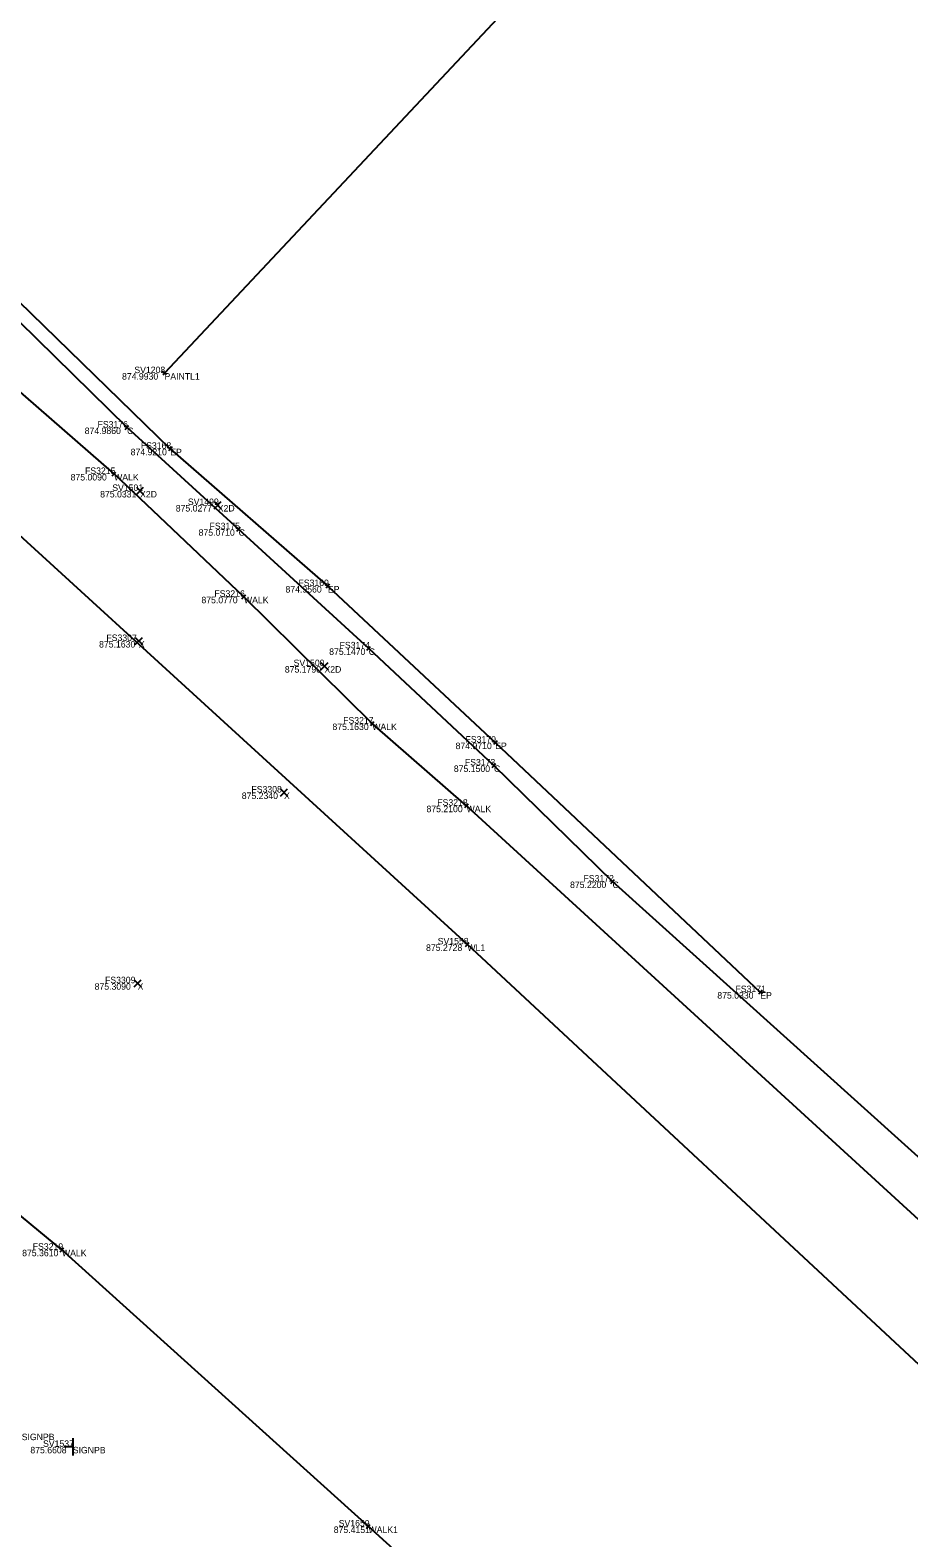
# Model space of a CAD drawing. Extents: x 1479481 to 1575806, y 316056 to 379927.
# Drawn here: x 1480189.17 to 1480197.29, y 379370.17 to 379384.1 of the extents above; entities that cross this region are included whole.
import ezdxf

# ---------------------------------------------------------------- set-up
doc = ezdxf.new("R2010")
doc.units = 0
for name, color, linetype in [('PM_X_Crosswalk', 7, 'Continuous'), ('PV_X_Curb', 7, 'Continuous'), ('PV_X_EOP', 7, 'Continuous'), ('PV_X_Walk', 7, 'Continuous'), ('SN_X_Public', 7, 'Continuous'), ('SV_X_Random_Point', 7, 'Continuous'), ('SV_X_Shot_Marker', 7, 'Continuous'), ('SV_X_Text_Comment', 7, 'Continuous'), ('SV_X_Text_Elevation', 7, 'Continuous'), ('SV_X_Text_Name', 7, 'Continuous'), ('UT_X_Water', 7, 'Continuous')]:
    doc.layers.add(name, color=color, linetype=linetype)

msp = doc.modelspace()

# ---------------------------------------------------------------- linework, layer by layer
at = {"layer": 'PM_X_Crosswalk'}
msp.add_lwpolyline([(1480217.07, 379409.327), (1480190.411, 379380.931)], dxfattribs=at)
at = {"layer": 'PV_X_Curb'}
for points in [[(1480200.436, 379370.31), (1480193.202, 379376.933), (1480192.331, 379377.692), (1480191.145, 379378.864), (1480189.945, 379379.999), (1480188.405, 379381.34), (1480186.948, 379382.631), (1480185.159, 379383.837), (1480183.612, 379384.764), (1480182.42, 379385.277), (1480180.94, 379385.773), (1480179.383, 379386.306), (1480178.708, 379386.55), (1480176.982, 379386.784), (1480175.084, 379387.087), (1480173.11, 379387.257), (1480172.166, 379387.208), (1480170.557, 379387.026), (1480168.815, 379386.8), (1480167.667, 379386.487), (1480166.614, 379386.24), (1480165.014, 379385.711), (1480163.297, 379385.035), (1480160.165, 379383.332)], [(1480200.731, 379370.664), (1480194.552, 379376.232), (1480193.456, 379377.305), (1480192.298, 379378.387), (1480191.096, 379379.488), (1480190.065, 379380.428), (1480189.066, 379381.408), (1480187.797, 379382.465), (1480186.696, 379383.309), (1480185.265, 379384.273), (1480183.824, 379385.018), (1480182.233, 379385.673), (1480180.762, 379386.381), (1480178.806, 379386.86)]]:
    msp.add_lwpolyline(points, dxfattribs=at)
at = {"layer": 'PV_X_EOP'}
msp.add_lwpolyline([(1480162.636, 379385.472), (1480163.801, 379386.077), (1480165.418, 379386.485), (1480167.155, 379386.981), (1480168.73, 379387.376), (1480170.459, 379387.707), (1480172.465, 379387.875), (1480174.363, 379387.724), (1480176.285, 379387.6), (1480178.413, 379387.246), (1480180.385, 379386.755), (1480182.516, 379385.858), (1480184.495, 379384.826), (1480186.137, 379383.794), (1480187.578, 379382.895), (1480189.061, 379381.596), (1480190.464, 379380.232), (1480191.921, 379378.963), (1480193.467, 379377.516), (1480195.917, 379375.21)], dxfattribs=at)
at = {"layer": 'PV_X_Walk'}
for points in [[(1480189.463, 379372.829), (1480188.36, 379373.736), (1480187.048, 379374.83), (1480185.76, 379375.931), (1480184.672, 379376.824), (1480183.309, 379377.92), (1480181.92, 379379.052), (1480180.82, 379379.987), (1480179.405, 379381.013), (1480178.224, 379381.663), (1480176.75, 379382.48), (1480175.258, 379382.991), (1480173.616, 379383.331), (1480171.941, 379383.389), (1480170.042, 379383.312), (1480168.62, 379383.135), (1480167.121, 379382.898), (1480164.933, 379381.864)], [(1480327.959, 379242.083), (1480313.163, 379256.356), (1480297.576, 379270.674), (1480283.951, 379284.205), (1480267.344, 379299.69), (1480258.509, 379307.782), (1480244.036, 379321.372), (1480229.243, 379335.021), (1480213.414, 379349.982), (1480196.806, 379366.202), (1480192.296, 379370.271), (1480189.463, 379372.829)]]:
    msp.add_lwpolyline(points, dxfattribs=at)
at = {"layer": 'SN_X_Public'}
for p, q in [((1480189.563, 379371.087), (1480189.563, 379370.927)), ((1480189.563, 379371.007), (1480189.483, 379371.007))]:
    msp.add_line(p, q, dxfattribs=at)
at = {"layer": 'SV_X_Random_Point'}
for p, q in [((1480190.152, 379379.809), (1480190.218, 379379.876)), ((1480190.152, 379379.876), (1480190.218, 379379.809)), ((1480190.87, 379379.678), (1480190.936, 379379.745)), ((1480190.87, 379379.745), (1480190.936, 379379.678)), ((1480190.141, 379378.422), (1480190.207, 379378.488)), ((1480190.141, 379378.488), (1480190.207, 379378.422)), ((1480191.856, 379378.189), (1480191.922, 379378.256)), ((1480191.856, 379378.256), (1480191.922, 379378.189)), ((1480191.482, 379377.022), (1480191.548, 379377.088)), ((1480191.482, 379377.088), (1480191.548, 379377.022)), ((1480190.129, 379375.259), (1480190.195, 379375.325)), ((1480190.129, 379375.325), (1480190.195, 379375.259))]:
    msp.add_line(p, q, dxfattribs=at)
at = {"layer": 'SV_X_Shot_Marker'}
for p, q in [((1480190.429, 379380.914), (1480190.393, 379380.948)), ((1480190.428, 379380.949), (1480190.394, 379380.912)), ((1480190.411, 379380.931), (1480190.411, 379380.931)), ((1480190.083, 379380.411), (1480190.047, 379380.445)), ((1480190.048, 379380.41), (1480190.082, 379380.446)), ((1480190.065, 379380.428), (1480190.065, 379380.428)), ((1480190.446, 379380.249), (1480190.482, 379380.215)), ((1480190.481, 379380.25), (1480190.447, 379380.214)), ((1480190.464, 379380.232), (1480190.464, 379380.232)), ((1480189.963, 379379.982), (1480189.927, 379380.016)), ((1480189.928, 379379.981), (1480189.962, 379380.017)), ((1480189.945, 379379.999), (1480189.945, 379379.999)), ((1480191.114, 379379.471), (1480191.078, 379379.505)), ((1480191.079, 379379.47), (1480191.113, 379379.506)), ((1480191.096, 379379.488), (1480191.096, 379379.488)), ((1480191.902, 379378.979), (1480191.94, 379378.947)), ((1480191.937, 379378.982), (1480191.905, 379378.944)), ((1480191.127, 379378.846), (1480191.163, 379378.882)), ((1480191.163, 379378.846), (1480191.127, 379378.882)), ((1480191.145, 379378.864), (1480191.145, 379378.864)), ((1480191.921, 379378.963), (1480191.921, 379378.963)), ((1480192.316, 379378.37), (1480192.28, 379378.404)), ((1480192.281, 379378.369), (1480192.315, 379378.405)), ((1480192.298, 379378.387), (1480192.298, 379378.387)), ((1480192.35, 379377.676), (1480192.312, 379377.708)), ((1480192.315, 379377.673), (1480192.347, 379377.711)), ((1480192.331, 379377.692), (1480192.331, 379377.692)), ((1480193.449, 379377.533), (1480193.485, 379377.499)), ((1480193.484, 379377.534), (1480193.45, 379377.498)), ((1480193.467, 379377.516), (1480193.467, 379377.516)), ((1480193.474, 379377.288), (1480193.438, 379377.323)), ((1480193.439, 379377.287), (1480193.473, 379377.323)), ((1480193.456, 379377.305), (1480193.456, 379377.305)), ((1480193.22, 379376.916), (1480193.184, 379376.95)), ((1480193.185, 379376.915), (1480193.219, 379376.951)), ((1480193.202, 379376.933), (1480193.202, 379376.933)), ((1480194.571, 379376.215), (1480194.533, 379376.249)), ((1480194.535, 379376.213), (1480194.569, 379376.251)), ((1480194.552, 379376.232), (1480194.552, 379376.232)), ((1480193.228, 379375.634), (1480193.192, 379375.668)), ((1480193.193, 379375.633), (1480193.227, 379375.67)), ((1480193.21, 379375.651), (1480193.21, 379375.651)), ((1480195.899, 379375.227), (1480195.935, 379375.193)), ((1480195.934, 379375.228), (1480195.9, 379375.192)), ((1480195.917, 379375.21), (1480195.917, 379375.21)), ((1480189.482, 379372.813), (1480189.444, 379372.845)), ((1480189.447, 379372.81), (1480189.479, 379372.848)), ((1480189.463, 379372.829), (1480189.463, 379372.829)), ((1480192.315, 379370.255), (1480192.277, 379370.288)), ((1480192.279, 379370.253), (1480192.313, 379370.29)), ((1480192.296, 379370.271), (1480192.296, 379370.271))]:
    msp.add_line(p, q, dxfattribs=at)
at = {"layer": 'UT_X_Water'}
msp.add_lwpolyline([(1480234.677, 379335.863), (1480225.088, 379345.601), (1480208.322, 379361.342), (1480207.346, 379362.25), (1480199.528, 379369.768), (1480193.21, 379375.651), (1480182.823, 379385.139), (1480177.927, 379389.525), (1480169.423, 379398.321), (1480161.035, 379406.189), (1480144.924, 379421.019), (1480134.739, 379430.559), (1480121.485, 379441.998), (1480113.085, 379450.369), (1480106.418, 379456.915), (1480094.539, 379467.985), (1480089.15, 379472.551), (1480086.751, 379474.713), (1480073.459, 379487.337), (1480068.123, 379493.187), (1480050.678, 379510.207), (1480044.404, 379515.873)], dxfattribs=at)

# ---------------------------------------------------------------- texts
at = {"layer": 'SV_X_Text_Comment'}
for s, p in [('PAINTL1', (1480190.411, 379380.871)), ('C', (1480190.065, 379380.368)), ('EP', (1480190.464, 379380.172)), ('WALK', (1480189.945, 379379.939)), ('X2D', (1480190.185, 379379.782)), ('X2D', (1480190.903, 379379.652)), ('C', (1480191.096, 379379.428)), ('WALK', (1480191.145, 379378.804)), ('EP', (1480191.921, 379378.903)), ('X', (1480190.174, 379378.395)), ('C', (1480192.298, 379378.327)), ('X2D', (1480191.889, 379378.163)), ('WALK', (1480192.331, 379377.632)), ('EP', (1480193.467, 379377.456)), ('C', (1480193.456, 379377.245)), ('X', (1480191.515, 379376.995)), ('WALK', (1480193.202, 379376.873)), ('C', (1480194.552, 379376.172)), ('WL1', (1480193.21, 379375.591)), ('X', (1480190.162, 379375.232)), ('EP', (1480195.917, 379375.15)), ('WALK', (1480189.463, 379372.769)), ('SIGNPB', (1480189.091, 379371.069)), ('SIGNPB', (1480189.563, 379370.947)), ('WALK1', (1480192.296, 379370.211))]:
    msp.add_text(s, height=0.06, dxfattribs=at).set_placement(p)
at = {"layer": 'SV_X_Text_Elevation'}
for s, p in [('874.9930', (1480190.018, 379380.871)), ('874.9860', (1480189.673, 379380.368)), ('874.9210', (1480190.098, 379380.172)), ('875.0090', (1480189.543, 379379.939)), ('875.0331', (1480189.816, 379379.782)), ('875.0277', (1480190.515, 379379.652)), ('875.0710', (1480190.726, 379379.428)), ('875.0770', (1480190.752, 379378.804)), ('874.9560', (1480191.529, 379378.903)), ('875.1630', (1480189.806, 379378.395)), ('875.1470', (1480191.933, 379378.327)), ('875.1790', (1480191.523, 379378.163)), ('875.1630', (1480191.963, 379377.632)), ('874.9710', (1480193.101, 379377.456)), ('875.1500', (1480193.085, 379377.245)), ('875.2340', (1480191.125, 379376.995)), ('875.2100', (1480192.832, 379376.873)), ('875.2200', (1480194.159, 379376.172)), ('875.2728', (1480192.828, 379375.591)), ('875.3090', (1480189.765, 379375.232)), ('875.0330', (1480195.52, 379375.15)), ('875.3610', (1480189.095, 379372.769)), ('875.6608', (1480189.171, 379370.947)), ('875.4151', (1480191.975, 379370.211))]:
    msp.add_text(s, height=0.06, dxfattribs=at).set_placement(p)
at = {"layer": 'SV_X_Text_Name'}
for s, p in [('SV1208', (1480190.132, 379380.931)), ('FS3176', (1480189.792, 379380.428)), ('FS3168', (1480190.192, 379380.232)), ('FS3215', (1480189.676, 379379.999)), ('SV1501', (1480189.928, 379379.842)), ('SV1499', (1480190.627, 379379.712)), ('FS3175', (1480190.827, 379379.488)), ('FS3169', (1480191.649, 379378.963)), ('FS3216', (1480190.872, 379378.864)), ('FS3307', (1480189.874, 379378.455)), ('FS3174', (1480192.029, 379378.387)), ('SV1500', (1480191.604, 379378.223)), ('FS3217', (1480192.062, 379377.692)), ('FS3170', (1480193.193, 379377.516)), ('FS3173', (1480193.187, 379377.305)), ('FS3308', (1480191.214, 379377.055)), ('FS3218', (1480192.932, 379376.933)), ('FS3172', (1480194.283, 379376.232)), ('SV1558', (1480192.936, 379375.651)), ('FS3309', (1480189.861, 379375.292)), ('FS3171', (1480195.688, 379375.21)), ('FS3219', (1480189.193, 379372.829)), ('SV1537', (1480189.288, 379371.007)), ('SV1659', (1480192.021, 379370.271))]:
    msp.add_text(s, height=0.06, dxfattribs=at).set_placement(p)

doc.saveas('drawing.dxf')
